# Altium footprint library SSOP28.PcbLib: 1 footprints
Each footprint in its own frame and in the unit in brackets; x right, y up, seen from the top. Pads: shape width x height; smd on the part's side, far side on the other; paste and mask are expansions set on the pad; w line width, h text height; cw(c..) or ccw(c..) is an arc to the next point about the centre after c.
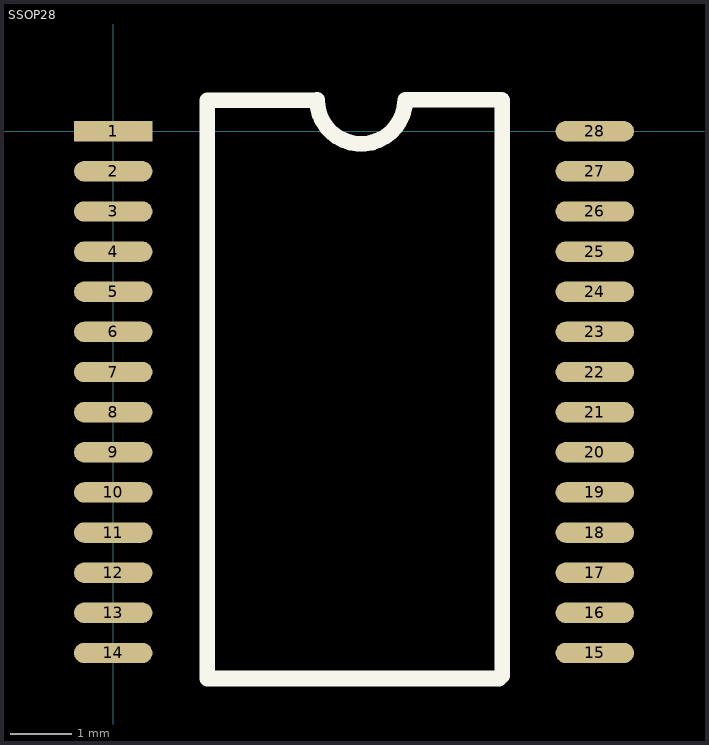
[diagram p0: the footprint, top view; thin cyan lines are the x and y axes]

## SSOP28 [mm]
pads (28):
  rect 1.27x0.33 smd: 1(0,0)
  oval 1.27x0.33 smd: 2(0,-0.65) 3(0,-1.3) 4(0,-1.95) 5(0,-2.6) 6(0,-3.25) 7(0,-3.9) 8(0,-4.55) 9(0,-5.2) 10(0,-5.85) 11(0,-6.5) 12(0,-7.15) 13(0,-7.8) 14(0,-8.45) 15(7.8,-8.45) 16(7.8,-7.8) 17(7.8,-7.15) 18(7.8,-6.5) 19(7.8,-5.85) 20(7.8,-5.2) 21(7.8,-4.55) 22(7.8,-3.9) 23(7.8,-3.25) 24(7.8,-2.6) 25(7.8,-1.95) 26(7.8,-1.3) 27(7.8,-0.65) 28(7.8,0)
Top Overlay:
  lines w0.254: 1.524,-8.865 6.248,-8.865 6.299,-8.814 6.299,0.5 6.291,0.508 4.728,0.508 cw(c4.015,0.508) 3.302,0.508 3.294,0.5 1.524,0.5 1.524,-8.865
